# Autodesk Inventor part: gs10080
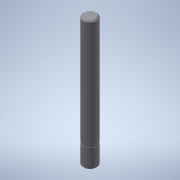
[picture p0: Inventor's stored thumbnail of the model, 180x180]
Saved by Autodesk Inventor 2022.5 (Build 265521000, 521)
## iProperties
Created: 2016-12
Part Number: gs10080
Material: 一般
Document SubType Name: Modeling
Designer: imaocorp
Density: 1 g/cm^3
Appearance: 既定
Author: imaocorp
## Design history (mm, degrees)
node "gs10080.x_t1"
node "gs10080"
node "Base1"
